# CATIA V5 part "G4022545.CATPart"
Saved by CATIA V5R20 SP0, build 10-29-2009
Part number: G4022545
Revision: 3
Definition: design
Nomenclature: G4022545
Source: made
Description: NOT SPECIFIED
Bounding box of the stored display mesh (mm): x -18 to 45, y -17.817 to 17.817, z -18 to 18
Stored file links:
  C:\Users\Raffaele\Desktop\3D X SITO CF\BOLEX\26-BUSH REF 402\G4022545.CATPart
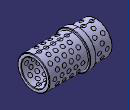
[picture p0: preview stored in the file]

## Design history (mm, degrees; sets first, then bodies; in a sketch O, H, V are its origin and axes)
Body1 "MANIFOLD_SOLID_BREP #13907" (main body)
  Solid1: solid without history
Body2 "MANIFOLD_SOLID_BREP #14058"
  Solid2: solid without history
Body3 "MANIFOLD_SOLID_BREP #14209"
  Solid3: solid without history
Body4 "MANIFOLD_SOLID_BREP #14360"
  Solid4: solid without history
Body5 "MANIFOLD_SOLID_BREP #14511"
  Solid5: solid without history
Body6 "MANIFOLD_SOLID_BREP #14660"
  Solid6: solid without history
Body7 "MANIFOLD_SOLID_BREP #14809"
  Solid7: solid without history
Body8 "MANIFOLD_SOLID_BREP #14958"
  Solid8: solid without history
Body9 "MANIFOLD_SOLID_BREP #15107"
  Solid9: solid without history
Body10 "MANIFOLD_SOLID_BREP #15256"
  Solid10: solid without history
Body11 "MANIFOLD_SOLID_BREP #15405"
  Solid11: solid without history
Body12 "MANIFOLD_SOLID_BREP #15554"
  Solid12: solid without history
Body13 "MANIFOLD_SOLID_BREP #15703"
  Solid13: solid without history
Body14 "MANIFOLD_SOLID_BREP #15852"
  Solid14: solid without history
Body15 "MANIFOLD_SOLID_BREP #16001"
  Solid15: solid without history
Body16 "MANIFOLD_SOLID_BREP #16150"
  Solid16: solid without history
Body17 "MANIFOLD_SOLID_BREP #16299"
  Solid17: solid without history
Body18 "MANIFOLD_SOLID_BREP #16448"
  Solid18: solid without history
Body19 "MANIFOLD_SOLID_BREP #16597"
  Solid19: solid without history
Body20 "MANIFOLD_SOLID_BREP #16746"
  Solid20: solid without history
Body21 "MANIFOLD_SOLID_BREP #16895"
  Solid21: solid without history
Body22 "MANIFOLD_SOLID_BREP #17044"
  Solid22: solid without history
Body23 "MANIFOLD_SOLID_BREP #17193"
  Solid23: solid without history
Body24 "MANIFOLD_SOLID_BREP #17342"
  Solid24: solid without history
Body25 "MANIFOLD_SOLID_BREP #17491"
  Solid25: solid without history
Body26 "MANIFOLD_SOLID_BREP #17640"
  Solid26: solid without history
Body27 "MANIFOLD_SOLID_BREP #17789"
  Solid27: solid without history
Body28 "MANIFOLD_SOLID_BREP #17938"
  Solid28: solid without history
Body29 "MANIFOLD_SOLID_BREP #18087"
  Solid29: solid without history
Body30 "MANIFOLD_SOLID_BREP #18236"
  Solid30: solid without history
Body31 "MANIFOLD_SOLID_BREP #18385"
  Solid31: solid without history
Body32 "MANIFOLD_SOLID_BREP #18536"
  Solid32: solid without history
Body33 "MANIFOLD_SOLID_BREP #18687"
  Solid33: solid without history
Body34 "MANIFOLD_SOLID_BREP #18836"
  Solid34: solid without history
Body35 "MANIFOLD_SOLID_BREP #18985"
  Solid35: solid without history
Body36 "MANIFOLD_SOLID_BREP #19134"
  Solid36: solid without history
Body37 "MANIFOLD_SOLID_BREP #19283"
  Solid37: solid without history
Body38 "MANIFOLD_SOLID_BREP #19432"
  Solid38: solid without history
Body39 "MANIFOLD_SOLID_BREP #19581"
  Solid39: solid without history
Body40 "MANIFOLD_SOLID_BREP #19730"
  Solid40: solid without history
Body41 "MANIFOLD_SOLID_BREP #19879"
  Solid41: solid without history
Body42 "MANIFOLD_SOLID_BREP #20028"
  Solid42: solid without history
Body43 "MANIFOLD_SOLID_BREP #20177"
  Solid43: solid without history
Body44 "MANIFOLD_SOLID_BREP #20326"
  Solid44: solid without history
Body45 "MANIFOLD_SOLID_BREP #20475"
  Solid45: solid without history
Body46 "MANIFOLD_SOLID_BREP #20624"
  Solid46: solid without history
Body47 "MANIFOLD_SOLID_BREP #20773"
  Solid47: solid without history
Body48 "MANIFOLD_SOLID_BREP #20922"
  Solid48: solid without history
Body49 "MANIFOLD_SOLID_BREP #21071"
  Solid49: solid without history
Body50 "MANIFOLD_SOLID_BREP #21220"
  Solid50: solid without history
Body51 "MANIFOLD_SOLID_BREP #21369"
  Solid51: solid without history
Body52 "MANIFOLD_SOLID_BREP #21518"
  Solid52: solid without history
Body53 "MANIFOLD_SOLID_BREP #21667"
  Solid53: solid without history
Body54 "MANIFOLD_SOLID_BREP #21818"
  Solid54: solid without history
Body55 "MANIFOLD_SOLID_BREP #21969"
  Solid55: solid without history
Body56 "MANIFOLD_SOLID_BREP #22120"
  Solid56: solid without history
Body57 "MANIFOLD_SOLID_BREP #22271"
  Solid57: solid without history
Body58 "MANIFOLD_SOLID_BREP #22420"
  Solid58: solid without history
Body59 "MANIFOLD_SOLID_BREP #22569"
  Solid59: solid without history
Body60 "MANIFOLD_SOLID_BREP #22718"
  Solid60: solid without history
Body61 "MANIFOLD_SOLID_BREP #22867"
  Solid61: solid without history
Body62 "MANIFOLD_SOLID_BREP #23016"
  Solid62: solid without history
Body63 "MANIFOLD_SOLID_BREP #23165"
  Solid63: solid without history
Body64 "MANIFOLD_SOLID_BREP #23314"
  Solid64: solid without history
Body65 "MANIFOLD_SOLID_BREP #23463"
  Solid65: solid without history
Body66 "MANIFOLD_SOLID_BREP #23612"
  Solid66: solid without history
Body67 "MANIFOLD_SOLID_BREP #23761"
  Solid67: solid without history
Body68 "MANIFOLD_SOLID_BREP #23910"
  Solid68: solid without history
Body69 "MANIFOLD_SOLID_BREP #24059"
  Solid69: solid without history
Body70 "MANIFOLD_SOLID_BREP #24208"
  Solid70: solid without history
Body71 "MANIFOLD_SOLID_BREP #24357"
  Solid71: solid without history
Body72 "MANIFOLD_SOLID_BREP #24508"
  Solid72: solid without history
Body73 "MANIFOLD_SOLID_BREP #24659"
  Solid73: solid without history
Body74 "MANIFOLD_SOLID_BREP #24808"
  Solid74: solid without history
Body75 "MANIFOLD_SOLID_BREP #24957"
  Solid75: solid without history
Body76 "MANIFOLD_SOLID_BREP #25106"
  Solid76: solid without history
Body77 "MANIFOLD_SOLID_BREP #25255"
  Solid77: solid without history
Body78 "MANIFOLD_SOLID_BREP #25404"
  Solid78: solid without history
Body79 "MANIFOLD_SOLID_BREP #25553"
  Solid79: solid without history
Body80 "MANIFOLD_SOLID_BREP #25702"
  Solid80: solid without history
Body81 "MANIFOLD_SOLID_BREP #25851"
  Solid81: solid without history
Body82 "MANIFOLD_SOLID_BREP #26000"
  Solid82: solid without history
Body83 "MANIFOLD_SOLID_BREP #26149"
  Solid83: solid without history
Body84 "MANIFOLD_SOLID_BREP #26298"
  Solid84: solid without history
Body85 "MANIFOLD_SOLID_BREP #26447"
  Solid85: solid without history
Body86 "MANIFOLD_SOLID_BREP #26596"
  Solid86: solid without history
Body87 "MANIFOLD_SOLID_BREP #26745"
  Solid87: solid without history
Body88 "MANIFOLD_SOLID_BREP #26896"
  Solid88: solid without history
Body89 "MANIFOLD_SOLID_BREP #27047"
  Solid89: solid without history
Body90 "MANIFOLD_SOLID_BREP #27196"
  Solid90: solid without history
Body91 "MANIFOLD_SOLID_BREP #27345"
  Solid91: solid without history
Body92 "MANIFOLD_SOLID_BREP #27494"
  Solid92: solid without history
Body93 "MANIFOLD_SOLID_BREP #27643"
  Solid93: solid without history
Body94 "MANIFOLD_SOLID_BREP #27792"
  Solid94: solid without history
Body95 "MANIFOLD_SOLID_BREP #27941"
  Solid95: solid without history
Body96 "MANIFOLD_SOLID_BREP #28090"
  Solid96: solid without history
Body97 "MANIFOLD_SOLID_BREP #28239"
  Solid97: solid without history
